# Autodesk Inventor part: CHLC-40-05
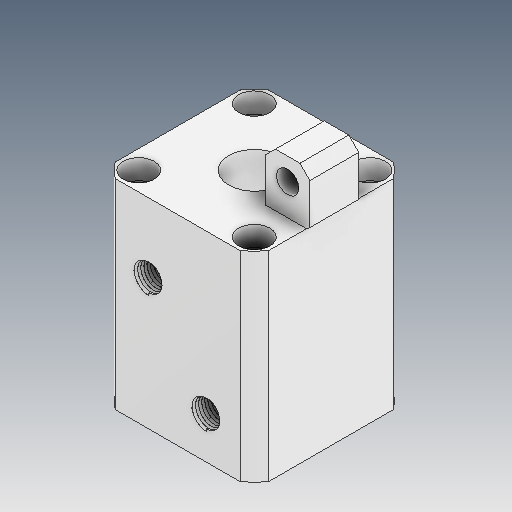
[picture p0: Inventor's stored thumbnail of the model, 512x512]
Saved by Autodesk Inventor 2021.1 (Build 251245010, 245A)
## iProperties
Created: 2021-05
Part Number: CHLC-40-05
Material: Ogólny
Document SubType Name: Modeling
Designer: user
Density: 1 g/cm^3
Appearance: Domyślna
Author: user
Revision Number: ÈÎºÎ
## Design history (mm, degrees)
feature "ÊäÈë1"
node "Bryła1"
